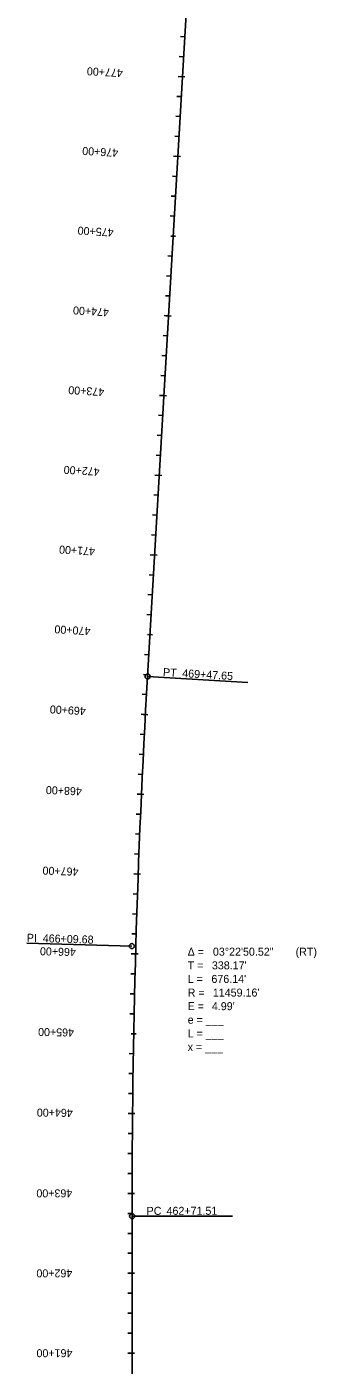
# Model space of a CAD drawing. Extents: x 23417911 to 23421158, y 6737892 to 6791804.
# Drawn here: x 23420697 to 23421061, y 6771582 to 6773259 of the extents above; entities that cross this region are included whole.
import ezdxf

# ---------------------------------------------------------------- set-up
doc = ezdxf.new("R2010")
doc.units = 0
for name, color, linetype in [('Alignment', 7, 'Continuous'), ('TextAlignment', 7, 'Continuous'), ('TextAlignmentLrg', 7, 'Continuous'), ('TextAlignmentSml', 7, 'Continuous')]:
    doc.layers.add(name, color=color, linetype=linetype)

msp = doc.modelspace()

# ---------------------------------------------------------------- linework, layer by layer
at = {"layer": 'Alignment'}
for p, q in [((23420848.9, 6772444.9), (23420902.4, 6773361.8)), ((23420848.9, 6772444.9), (23420902.4, 6773361.8)), ((23420834.6, 6764732), (23420829.5, 6771769.1)), ((23420834.6, 6764732), (23420829.5, 6771769.1))]:
    msp.add_line(p, q, dxfattribs=at)
msp.add_arc((23432288.6, 6771777.4), 11459.2, 176.66087, 180.04157, dxfattribs=at)
msp.add_arc((23432288.6, 6771777.4), 11459.2, 176.66087, 180.04157, dxfattribs=at)
at = {"layer": 'TextAlignment'}
for p, q in [((23420848.9, 6772444.9), (23420974.7, 6772437.5)), ((23420974.7, 6772437.5), (23420974.7, 6772437.5)), ((23420829.2, 6772107.3), (23420697.3, 6772111.1)), ((23420697.3, 6772111.1), (23420697.3, 6772111.1)), ((23420829.5, 6771769.1), (23420955.5, 6771769.2)), ((23420955.5, 6771769.2), (23420955.5, 6771769.2))]:
    msp.add_line(p, q, dxfattribs=at)
for centre in [(23420848.9, 6772444.9), (23420829.2, 6772107.3), (23420829.5, 6771769.1)]:
    msp.add_circle(centre, 3.12, dxfattribs=at)
at = {"layer": 'TextAlignmentLrg'}
for p, q in [((23420892.7, 6773195.9), (23420887.3, 6773196.3)), ((23420886.9, 6773096.1), (23420881.5, 6773096.4)), ((23420878, 6772996.5), (23420884.1, 6772996.1)), ((23420875.3, 6772896.5), (23420869.8, 6772896.8)), ((23420869.4, 6772796.6), (23420864, 6772796.9)), ((23420863.6, 6772696.8), (23420858.2, 6772697.1)), ((23420857.8, 6772597), (23420852.3, 6772597.3)), ((23420848.9, 6772497.3), (23420855, 6772497)), ((23420846.2, 6772397.3), (23420840.8, 6772397.6)), ((23420841.3, 6772297.4), (23420835.8, 6772297.7)), ((23420837.2, 6772197.5), (23420831.7, 6772197.7)), ((23420833.9, 6772097.6), (23420828.5, 6772097.7)), ((23420828.5, 6771997.6), (23420834.6, 6771997.5)), ((23420830.1, 6771897.6), (23420824.6, 6771897.7)), ((23420829.5, 6771797.6), (23420824, 6771797.6)), ((23420829.5, 6771697.6), (23420824, 6771697.6)), ((23420829.6, 6771597.6), (23420824.1, 6771597.6))]:
    msp.add_line(p, q, dxfattribs=at)
at = {"layer": 'TextAlignmentSml'}
for p, q in [((23420895.6, 6773245.9), (23420890.2, 6773246.2)), ((23420894.2, 6773220.9), (23420888.7, 6773221.2)), ((23420889.7, 6773196.1), (23420895.8, 6773195.8)), ((23420891.3, 6773171), (23420885.8, 6773171.3)), ((23420889.8, 6773146), (23420884.4, 6773146.4)), ((23420888.4, 6773121.1), (23420882.9, 6773121.4)), ((23420883.8, 6773096.3), (23420890, 6773095.9)), ((23420885.4, 6773071.2), (23420880, 6773071.5)), ((23420884, 6773046.2), (23420878.5, 6773046.5)), ((23420882.5, 6773021.2), (23420877.1, 6773021.6)), ((23420878, 6772996.5), (23420884.1, 6772996.1)), ((23420879.6, 6772971.3), (23420874.2, 6772971.6)), ((23420878.2, 6772946.4), (23420872.7, 6772946.7)), ((23420876.7, 6772921.4), (23420871.3, 6772921.7)), ((23420872.2, 6772896.6), (23420878.3, 6772896.3)), ((23420873.8, 6772871.5), (23420868.3, 6772871.8)), ((23420872.3, 6772846.5), (23420866.9, 6772846.9)), ((23420870.9, 6772821.6), (23420865.4, 6772821.9)), ((23420866.4, 6772796.8), (23420872.5, 6772796.4)), ((23420868, 6772771.7), (23420862.5, 6772772)), ((23420866.5, 6772746.7), (23420861.1, 6772747)), ((23420865.1, 6772721.8), (23420859.6, 6772722.1)), ((23420860.5, 6772697), (23420866.7, 6772696.6)), ((23420862.1, 6772671.8), (23420856.7, 6772672.2)), ((23420860.7, 6772646.9), (23420855.2, 6772647.2)), ((23420859.2, 6772621.9), (23420853.8, 6772622.2)), ((23420854.7, 6772597.1), (23420860.8, 6772596.8)), ((23420856.3, 6772572), (23420850.9, 6772572.3)), ((23420854.9, 6772547.1), (23420849.4, 6772547.4)), ((23420853.4, 6772522.1), (23420848, 6772522.4)), ((23420848.9, 6772497.3), (23420855, 6772497)), ((23420850.5, 6772472.2), (23420845, 6772472.5)), ((23420849, 6772447.2), (23420843.6, 6772447.5)), ((23420847.6, 6772422.3), (23420842.2, 6772422.6)), ((23420843.2, 6772397.5), (23420849.3, 6772397.1)), ((23420844.9, 6772372.3), (23420839.5, 6772372.6)), ((23420843.6, 6772347.4), (23420838.2, 6772347.6)), ((23420842.4, 6772322.4), (23420837, 6772322.7)), ((23420838.2, 6772297.6), (23420844.3, 6772297.3)), ((23420840.1, 6772272.4), (23420834.7, 6772272.7)), ((23420839.1, 6772247.5), (23420833.6, 6772247.7)), ((23420838.1, 6772222.5), (23420832.6, 6772222.7)), ((23420834.1, 6772197.6), (23420840.2, 6772197.4)), ((23420836.3, 6772172.5), (23420830.8, 6772172.7)), ((23420835.4, 6772147.5), (23420830, 6772147.7)), ((23420834.7, 6772122.6), (23420829.2, 6772122.7)), ((23420830.9, 6772097.6), (23420837, 6772097.5)), ((23420833.3, 6772072.6), (23420827.8, 6772072.7)), ((23420832.6, 6772047.6), (23420827.2, 6772047.7)), ((23420832.1, 6772022.6), (23420826.6, 6772022.7)), ((23420828.5, 6771997.6), (23420834.6, 6771997.5)), ((23420831.1, 6771972.6), (23420825.7, 6771972.7)), ((23420830.7, 6771947.6), (23420825.3, 6771947.7)), ((23420830.4, 6771922.6), (23420824.9, 6771922.7)), ((23420827, 6771897.6), (23420833.1, 6771897.6)), ((23420829.8, 6771872.6), (23420824.4, 6771872.6)), ((23420829.7, 6771847.6), (23420824.2, 6771847.6)), ((23420829.5, 6771822.6), (23420824.1, 6771822.6)), ((23420826.4, 6771797.6), (23420832.5, 6771797.6)), ((23420829.5, 6771772.6), (23420824, 6771772.6)), ((23420829.5, 6771747.6), (23420824, 6771747.6)), ((23420829.5, 6771722.6), (23420824, 6771722.6)), ((23420826.4, 6771697.6), (23420832.6, 6771697.6)), ((23420829.5, 6771672.6), (23420824.1, 6771672.6)), ((23420829.5, 6771647.6), (23420824.1, 6771647.6)), ((23420829.6, 6771622.6), (23420824.1, 6771622.6)), ((23420826.5, 6771597.6), (23420832.6, 6771597.6))]:
    msp.add_line(p, q, dxfattribs=at)

# ---------------------------------------------------------------- texts
at = {"layer": 'TextAlignment'}
for s, rotation, p in [('PT', 356.6609, (23420868, 6772445.5)), ('469+47.65', 356.6609, (23420892.2, 6772444.1)), ('PI ', 358.3512, (23420697.3, 6772112.8)), ('466+09.68', 358.3512, (23420717.3, 6772112.2)), ('PC', 0.0416, (23420847.7, 6771770.8)), ('462+71.51', 0.0416, (23420872.7, 6771770.8))]:
    msp.add_text(s, height=10.02, rotation=rotation, dxfattribs=at).set_placement(p)
for s, p in [('Δ = ', (23420899.2, 6772095.3)), ('03°22\'50.52"', (23420930.9, 6772095.3)), (' (RT)', (23421030.9, 6772095.3)), ('T = ', (23420899.2, 6772078.2)), ("338.17'", (23420929.6, 6772078.2)), ('L = ', (23420899.2, 6772061.2)), ("676.14'", (23420929, 6772061.2)), ('R = ', (23420899.2, 6772044.1)), ("11459.16'", (23420930.8, 6772044.1)), ('E = ', (23420899.2, 6772027.1)), ("4.99'", (23420929.6, 6772027.1)), ('e = ___ ', (23420899.2, 6772010.1)), ('L = ___', (23420899.2, 6771993)), ('x = ___', (23420899.2, 6771976))]:
    msp.add_text(s, height=10.02, dxfattribs=at).set_placement(p)
at = {"layer": 'TextAlignmentLrg'}
for s, rotation, p in [('475+00', 176.6609, (23420806.5, 6773005.7)), ('470+00', 176.6609, (23420777.4, 6772506.5)), ('465+00', 178.8991, (23420756.7, 6772004))]:
    msp.add_text(s, height=10.02, rotation=rotation, dxfattribs=at).set_placement(p)
at = {"layer": 'TextAlignmentSml'}
for s, rotation, p in [('477+00', 176.6609, (23420818.1, 6773205.3)), ('476+00', 176.6609, (23420812.3, 6773105.5)), ('475+00', 176.6609, (23420806.5, 6773005.7)), ('474+00', 176.6609, (23420800.7, 6772905.8)), ('473+00', 176.6609, (23420794.8, 6772806)), ('472+00', 176.6609, (23420789, 6772706.2)), ('471+00', 176.6609, (23420783.2, 6772606.3)), ('470+00', 176.6609, (23420777.4, 6772506.5)), ('469+00', 176.8991, (23420771.6, 6772406.4)), ('468+00', 177.3991, (23420766.6, 6772305.8)), ('467+00', 177.8991, (23420762.4, 6772205.3)), ('466+00', 178.3991, (23420759.1, 6772104.7)), ('465+00', 178.8991, (23420756.7, 6772004)), ('464+00', 179.3991, (23420755.1, 6771903.4)), ('463+00', 179.8991, (23420754.5, 6771802.7)), ('462+00', 180.0416, (23420754.5, 6771702.6)), ('461+00', 180.0416, (23420754.6, 6771602.6))]:
    msp.add_text(s, height=10.02, rotation=rotation, dxfattribs=at).set_placement(p)

doc.saveas('drawing.dxf')
